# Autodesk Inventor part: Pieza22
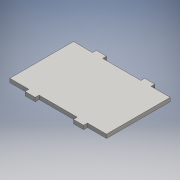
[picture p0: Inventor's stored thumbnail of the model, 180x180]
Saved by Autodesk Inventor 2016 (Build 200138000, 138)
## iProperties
Created: 2016-06
Part Number: Pieza22
Material: Genérico
Document SubType Name: Modeling
Designer: adm
Density: 1 g/cm^3
Appearance: Valor por defecto
Author: adm
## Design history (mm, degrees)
sketch "Boceto1"
  geometry: L1 (-38, -25)-(-38, 25); L2 (38, 25)-(38, -25); L3 (38, -25)-(-38, 25); L4 (-38, -25)-(38, 25); L5 (-15, 25)-(-15, 28); L6 (-15, 28)-(-23, 28); L7 (-23, 28)-(-23, 25); L8 (15, 25)-(15, 28); L9 (15, 28)-(23, 28); L10 (23, 28)-(23, 25); L11 (23, -28)-(23, -25); L12 (15, -25)-(15, -28); L13 (15, -28)-(23, -28); L14 (-15, -25)-(-15, -28); L15 (-23, -28)-(-23, -25); L16 (-15, -28)-(-23, -28); L17 (-38, 25)-(-23, 25); L18 (-15, 25)-(15, 25); L19 (23, 25)-(38, 25); L20 (-23, -25)-(-38, -25); L21 (38, -25)-(23, -25); L22 (15, -25)-(-15, -25); 1 further point
  constraints: 44 end point, 12 parallel, 3 horizontal, 3 perpendicular, 2 midpoint
  dimensions: "d0" = 50 distance of L2.start L2.end; "d1" = 76 distance of L2.end L1.start; "d2" = 30 distance between parallel lines of L8 L5; "d3" = 8 distance of L8.end L9.end; "d4" = 8 distance of L5.end L6.end; "d5" = 15 distance from line of point (0, 0) L8; "d6" = 3 distance of L8.start L8.end; "d7" = 3 distance of L5.start L5.end
extrude "Extrusión1" new body sketch "Boceto1" distance "d8" = 3; taper "d9" = 0 deg
node "Sólido1"
